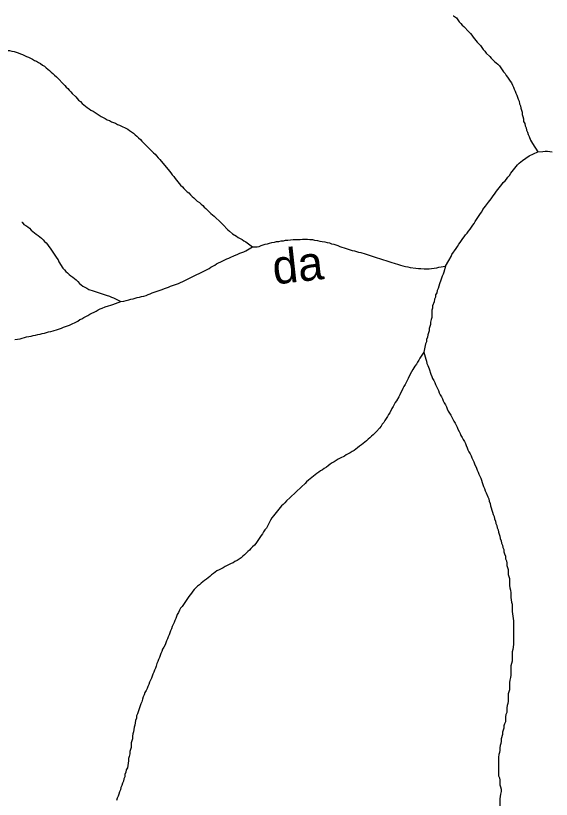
# Model space of a CAD drawing. Extents: x 652.3 to 678, y 7316.9 to 7344.9.
# Drawn here: x 675.65 to 676.905, y 7339.863 to 7341.699 of the extents above; entities that cross this region are included whole.
import ezdxf
from ezdxf.enums import TextEntityAlignment as Align

# ---------------------------------------------------------------- set-up
doc = ezdxf.new("R2010")
doc.units = 0
doc.header["$LTSCALE"] = 0.032
doc.layers.add('61', color=7, linetype='Continuous')
doc.layers.add('7', color=7, linetype='Continuous', lineweight=25)

msp = doc.modelspace()

# ---------------------------------------------------------------- linework, layer by layer
at = {"layer": '7'}
for points in [[(676.6749, 7341.6989), (676.6752, 7341.6987), (676.6824, 7341.6939), (676.6856, 7341.6892), (676.6888, 7341.6844), (676.6927, 7341.6804), (676.6959, 7341.6764), (676.6999, 7341.6733), (676.7118, 7341.6613), (676.715, 7341.6573), (676.7182, 7341.6534), (676.7214, 7341.6486), (676.7246, 7341.6446), (676.7309, 7341.6367), (676.7389, 7341.6287), (676.7421, 7341.6247), (676.7452, 7341.6199), (676.7492, 7341.616), (676.7524, 7341.6112), (676.7604, 7341.6032), (676.7635, 7341.5993), (676.7715, 7341.5913), (676.7755, 7341.5881), (676.7795, 7341.5849), (676.7834, 7341.581), (676.7866, 7341.577), (676.7898, 7341.5722), (676.793, 7341.5674), (676.7962, 7341.5634), (676.7986, 7341.5587), (676.8017, 7341.5547), (676.8081, 7341.5451), (676.8113, 7341.5412), (676.8137, 7341.5364), (676.8161, 7341.5316), (676.8177, 7341.5268), (676.82, 7341.5221), (676.8216, 7341.5173), (676.824, 7341.5125), (676.8272, 7341.503), (676.8296, 7341.4982), (676.8304, 7341.4926), (676.8328, 7341.4879), (676.8336, 7341.4823), (676.8368, 7341.4727), (676.8368, 7341.4672), (676.8383, 7341.4624), (676.8399, 7341.4568), (676.8399, 7341.4513), (676.8423, 7341.4465), (676.8431, 7341.4409), (676.8455, 7341.4361), (676.8463, 7341.4306), (676.8487, 7341.4258), (676.8503, 7341.4202), (676.8527, 7341.4154), (676.8558, 7341.4075), (676.8606, 7341.3995), (676.8734, 7341.3796)], [(675.6241, 7341.6176), (675.6353, 7341.6176), (675.6408, 7341.616), (675.6464, 7341.6152), (675.6559, 7341.612), (675.6607, 7341.6096), (675.6655, 7341.608), (675.675, 7341.6032)], [(675.675, 7341.6032), (675.6798, 7341.6016), (675.6894, 7341.5969), (675.6941, 7341.5937), (675.6989, 7341.5921), (675.7029, 7341.5889), (675.7077, 7341.5865), (675.7124, 7341.5833), (675.7172, 7341.5802), (675.7212, 7341.577), (675.7252, 7341.5738), (675.7292, 7341.5706), (675.7331, 7341.5666), (675.7371, 7341.5634), (675.7411, 7341.5595), (675.7451, 7341.5555), (675.765, 7341.5356), (675.7681, 7341.5316), (675.7721, 7341.5284), (675.7753, 7341.5245), (675.7793, 7341.5205), (675.7825, 7341.5165), (675.7904, 7341.5085), (675.7936, 7341.5046), (675.7968, 7341.5006), (675.8016, 7341.4974), (675.8055, 7341.4934), (675.8095, 7341.4902), (675.8135, 7341.4871), (675.8175, 7341.4839), (675.8222, 7341.4807), (675.8262, 7341.4775), (675.831, 7341.4751), (675.8358, 7341.4719), (675.8405, 7341.4688), (675.8453, 7341.4656), (675.8501, 7341.4624), (675.8549, 7341.46), (675.8596, 7341.4576), (675.8644, 7341.4552), (675.8692, 7341.4536), (675.874, 7341.4505), (675.8787, 7341.4489), (675.8835, 7341.4473), (675.8883, 7341.4441), (675.8931, 7341.4425), (675.9122, 7341.433), (675.9161, 7341.4298), (675.9209, 7341.4266), (675.9257, 7341.4234), (675.9297, 7341.4194), (675.9336, 7341.4162), (675.9376, 7341.4123), (675.9424, 7341.4091), (675.9456, 7341.4051), (675.9535, 7341.3971), (675.9567, 7341.3932), (675.9647, 7341.3852), (675.9687, 7341.3812), (675.9726, 7341.3773), (675.9766, 7341.3741), (675.9798, 7341.3701), (675.9838, 7341.3661), (675.9878, 7341.3621), (676.01, 7341.3343), (676.0132, 7341.3303), (676.0164, 7341.3263), (676.0204, 7341.3224), (676.0236, 7341.3176), (676.0363, 7341.3017), (676.0403, 7341.2977), (676.0434, 7341.2937), (676.0474, 7341.2897), (676.0514, 7341.2865), (676.0554, 7341.2834), (676.0594, 7341.2794), (676.0633, 7341.2754), (676.0673, 7341.2722), (676.0713, 7341.2682), (676.0753, 7341.2643), (676.0801, 7341.2611), (676.084, 7341.2571), (676.088, 7341.2539), (676.0912, 7341.2499), (676.0952, 7341.2468), (676.0991, 7341.2428), (676.1031, 7341.2396), (676.1071, 7341.2356), (676.1111, 7341.2324), (676.1151, 7341.2293), (676.131, 7341.2133), (676.135, 7341.2094), (676.1469, 7341.1974), (676.1509, 7341.1942), (676.158, 7341.1879), (676.1668, 7341.1823), (676.1708, 7341.1791), (676.1803, 7341.1744), (676.1843, 7341.1712), (676.1891, 7341.1688), (676.205, 7341.1569)], [(676.6569, 7341.1123), (676.6649, 7341.125), (676.6697, 7341.1346), (676.672, 7341.1393), (676.6816, 7341.1537), (676.6848, 7341.1584), (676.688, 7341.1632), (676.6911, 7341.1672), (676.6975, 7341.1767), (676.7007, 7341.1807), (676.7039, 7341.1855), (676.7078, 7341.1895), (676.711, 7341.1942), (676.7142, 7341.199), (676.7174, 7341.203), (676.7206, 7341.2078), (676.7238, 7341.2118), (676.7261, 7341.2165), (676.7325, 7341.2261), (676.7357, 7341.2309), (676.7389, 7341.2356), (676.7421, 7341.2396), (676.7445, 7341.2444), (676.7508, 7341.2523), (676.7572, 7341.2619), (676.7635, 7341.2698), (676.7667, 7341.2746), (676.7731, 7341.2826), (676.7763, 7341.2873), (676.789, 7341.3033), (676.7922, 7341.308), (676.7962, 7341.312), (676.7994, 7341.316), (676.8025, 7341.3208), (676.8065, 7341.3247), (676.8097, 7341.3295), (676.8256, 7341.3494), (676.8296, 7341.3534), (676.8336, 7341.3566), (676.8375, 7341.3598), (676.8447, 7341.3653), (676.8527, 7341.3701), (676.8734, 7341.3796)], [(676.8734, 7341.3796), (676.8845, 7341.3804), (676.8901, 7341.3812), (676.8956, 7341.3812), (676.9012, 7341.3804), (676.9068, 7341.3796)], [(675.6645, 7341.2153), (675.6647, 7341.2149), (675.6687, 7341.2094), (675.6735, 7341.207), (675.6782, 7341.2038), (675.6822, 7341.2006), (675.6862, 7341.1966), (675.6902, 7341.1935), (675.6941, 7341.1903), (675.6981, 7341.1871), (675.7021, 7341.1839), (675.7061, 7341.1807), (675.7101, 7341.1775), (675.714, 7341.1736), (675.7172, 7341.1696), (675.7212, 7341.1664), (675.7244, 7341.1624), (675.7276, 7341.1584), (675.7307, 7341.1545), (675.7339, 7341.1497), (675.7403, 7341.1401), (675.7427, 7341.1354), (675.7459, 7341.1306), (675.749, 7341.1266), (675.7506, 7341.1218), (675.7602, 7341.1075), (675.7642, 7341.1035), (675.7673, 7341.0996), (675.7713, 7341.0964), (675.7753, 7341.0924), (675.7793, 7341.0892), (675.7833, 7341.086), (675.7872, 7341.0829), (675.7912, 7341.0797), (675.7952, 7341.0757), (675.7992, 7341.0717), (675.8032, 7341.0685), (675.8071, 7341.0653), (675.8119, 7341.063), (675.8167, 7341.0606), (675.8215, 7341.0574), (675.831, 7341.0542), (675.8358, 7341.0526), (675.8501, 7341.0478), (675.8549, 7341.0463), (675.862, 7341.0439), (675.8692, 7341.0415), (675.874, 7341.0391), (675.8787, 7341.0375), (675.8962, 7341.0295)], [(676.205, 7341.1569), (676.2153, 7341.1569), (676.2201, 7341.1584), (676.2249, 7341.16), (676.2344, 7341.1632), (676.24, 7341.164), (676.2448, 7341.1656), (676.2503, 7341.1672), (676.2559, 7341.168), (676.2607, 7341.1696), (676.2662, 7341.1696), (676.2718, 7341.1712), (676.2774, 7341.1712), (676.2822, 7341.1728), (676.2877, 7341.1728), (676.2933, 7341.1736), (676.2997, 7341.1744), (676.3164, 7341.1744), (676.3219, 7341.1752), (676.3331, 7341.1752), (676.3386, 7341.1744), (676.345, 7341.1744), (676.3498, 7341.1728), (676.357, 7341.172), (676.3625, 7341.1704), (676.3681, 7341.1696), (676.3737, 7341.1688), (676.3792, 7341.1672), (676.3848, 7341.1664), (676.3896, 7341.164), (676.3951, 7341.1632), (676.4047, 7341.16), (676.4095, 7341.1584), (676.4238, 7341.1537), (676.4286, 7341.1521), (676.4381, 7341.1489), (676.4437, 7341.1481), (676.4532, 7341.1449), (676.4588, 7341.1441), (676.4683, 7341.1409), (676.4731, 7341.1393), (676.4874, 7341.1346), (676.4922, 7341.133), (676.5065, 7341.1282), (676.5113, 7341.1266), (676.5169, 7341.125), (676.5264, 7341.1218), (676.5312, 7341.1202), (676.5368, 7341.1187), (676.5463, 7341.1155), (676.5511, 7341.1139), (676.5567, 7341.1131), (676.563, 7341.1115), (676.5686, 7341.1107), (676.5742, 7341.1091), (676.5869, 7341.1075), (676.5933, 7341.1067), (676.5988, 7341.1067), (676.6068, 7341.1059), (676.6187, 7341.1059), (676.6243, 7341.1067), (676.6299, 7341.1075), (676.6362, 7341.1083), (676.641, 7341.1099), (676.6569, 7341.1123)], [(675.8962, 7341.0295), (675.9034, 7341.0303), (675.909, 7341.0311), (675.9145, 7341.0327), (675.9193, 7341.0343), (675.9249, 7341.0351), (675.9344, 7341.0383), (675.94, 7341.0391), (675.9448, 7341.0407), (675.9504, 7341.0415), (675.9551, 7341.0431), (675.9599, 7341.0455), (675.9647, 7341.047), (675.9695, 7341.0494), (675.979, 7341.0526), (675.9838, 7341.0542), (675.9933, 7341.0574), (675.9981, 7341.0598), (676.0076, 7341.063), (676.0124, 7341.0653), (676.0172, 7341.0669), (676.0315, 7341.0717), (676.0363, 7341.0733), (676.0411, 7341.0757), (676.0458, 7341.0781), (676.0506, 7341.0805), (676.0745, 7341.0924), (676.0793, 7341.0948), (676.1031, 7341.1067), (676.1071, 7341.1099), (676.1119, 7341.1123), (676.1167, 7341.1139), (676.1206, 7341.1171), (676.135, 7341.1242), (676.1397, 7341.1266), (676.1445, 7341.129), (676.1493, 7341.1306), (676.154, 7341.133), (676.1612, 7341.1362), (676.17, 7341.1401), (676.1747, 7341.1425), (676.1843, 7341.1457), (676.1891, 7341.1481), (676.205, 7341.1569)], [(676.6569, 7341.1123), (676.6529, 7341.098), (676.6514, 7341.0932), (676.649, 7341.0884), (676.6474, 7341.0836), (676.6458, 7341.0789), (676.6426, 7341.0709), (676.6394, 7341.0598), (676.637, 7341.055), (676.6362, 7341.0494), (676.6331, 7341.0447), (676.6331, 7341.0391), (676.6307, 7341.0343), (676.6299, 7341.0287), (676.6267, 7341.0192), (676.6267, 7341.0136), (676.6251, 7341.0089), (676.6251, 7340.9913), (676.6235, 7340.9866), (676.6219, 7340.981), (676.6219, 7340.9754), (676.6187, 7340.9659), (676.6187, 7340.9603), (676.6155, 7340.9508), (676.6148, 7340.9452), (676.6124, 7340.9404), (676.6124, 7340.9349), (676.61, 7340.9301), (676.606, 7340.9102)], [(675.648, 7340.9404), (675.6544, 7340.9412), (675.6599, 7340.942), (675.6647, 7340.9436), (675.6703, 7340.9444), (675.675, 7340.946), (675.6806, 7340.9468), (675.6862, 7340.9476), (675.691, 7340.9492), (675.6965, 7340.95), (675.7013, 7340.9516), (675.7069, 7340.9524), (675.7116, 7340.954), (675.7172, 7340.9547), (675.722, 7340.9563), (675.7268, 7340.9579), (675.7323, 7340.9587), (675.7379, 7340.9603), (675.7475, 7340.9635), (675.7522, 7340.9651), (675.757, 7340.9667), (675.7618, 7340.9691), (675.7761, 7340.9738), (675.7952, 7340.9834), (675.8, 7340.9866), (675.8047, 7340.9882), (675.8095, 7340.9913), (675.8191, 7340.9961), (675.8238, 7340.9993), (675.8382, 7341.0065), (675.8429, 7341.0096), (675.8477, 7341.012), (675.8525, 7341.0136), (675.8596, 7341.0168), (675.8676, 7341.0192), (675.8724, 7341.0208), (675.8772, 7341.0224), (675.8962, 7341.0295)], [(676.606, 7340.9102), (676.5965, 7340.8967), (676.5941, 7340.8919), (676.5909, 7340.8871), (676.5885, 7340.8823), (676.5853, 7340.8776), (676.5805, 7340.8696), (676.5742, 7340.8585), (676.5694, 7340.8489), (676.567, 7340.8441), (676.5622, 7340.8346), (676.5591, 7340.8298), (676.5567, 7340.825), (676.5495, 7340.8107), (676.5471, 7340.806), (676.5423, 7340.7964), (676.5392, 7340.7924), (676.5344, 7340.7829), (676.5312, 7340.7781), (676.5264, 7340.7686), (676.5232, 7340.7646), (676.5209, 7340.7598), (676.5177, 7340.755), (676.5145, 7340.7503), (676.5121, 7340.7455), (676.5081, 7340.7415), (676.5057, 7340.7367), (676.5018, 7340.7327), (676.4954, 7340.7248), (676.4874, 7340.7168), (676.4835, 7340.7137), (676.4795, 7340.7097), (676.4755, 7340.7065), (676.4715, 7340.7025), (676.4676, 7340.6993), (676.4636, 7340.6961), (676.4596, 7340.693), (676.4556, 7340.6898), (676.4508, 7340.6866), (676.4469, 7340.6834), (676.4429, 7340.6802), (676.4381, 7340.6778), (676.4333, 7340.6747), (676.4286, 7340.6723), (676.4238, 7340.6699), (676.4198, 7340.6667), (676.4103, 7340.6619), (676.4055, 7340.6595), (676.4007, 7340.6564), (676.3959, 7340.6532), (676.3912, 7340.6508), (676.3864, 7340.6476), (676.3816, 7340.6444), (676.3776, 7340.6412), (676.3729, 7340.6381), (676.3689, 7340.6349), (676.3641, 7340.6325), (676.3601, 7340.6293), (676.3554, 7340.6261), (676.3514, 7340.6229), (676.3474, 7340.6198), (676.3434, 7340.6166), (676.3394, 7340.6134), (676.3355, 7340.6102), (676.3315, 7340.6062), (676.3283, 7340.6023), (676.3196, 7340.5951)], [(676.606, 7340.9102), (676.6108, 7340.8943), (676.6124, 7340.8895), (676.6132, 7340.8839), (676.6155, 7340.8792), (676.6187, 7340.8712), (676.6227, 7340.8585), (676.6251, 7340.8537), (676.6267, 7340.8489), (676.6291, 7340.8441), (676.6315, 7340.8394), (676.6331, 7340.8346), (676.6354, 7340.8298), (676.6378, 7340.825), (676.6402, 7340.8203), (676.6418, 7340.8155), (676.6442, 7340.8107), (676.6474, 7340.806), (676.6498, 7340.8012), (676.6514, 7340.7964), (676.6537, 7340.7916), (676.6569, 7340.7869), (676.6593, 7340.7821), (676.6609, 7340.7773), (676.6633, 7340.7725), (676.6665, 7340.7678), (676.6689, 7340.763), (676.672, 7340.7582), (676.6736, 7340.7534), (676.676, 7340.7487), (676.6792, 7340.7439), (676.684, 7340.7343), (676.6856, 7340.7296), (676.6888, 7340.7248), (676.6911, 7340.72), (676.6927, 7340.7152), (676.6959, 7340.7105), (676.6983, 7340.7057), (676.7015, 7340.7009), (676.7039, 7340.6961), (676.7055, 7340.6914), (676.7078, 7340.6866), (676.7094, 7340.6818), (676.7118, 7340.6771), (676.7142, 7340.6723), (676.7166, 7340.6675), (676.7182, 7340.6627), (676.7206, 7340.658), (676.723, 7340.6532), (676.7246, 7340.6484), (676.7293, 7340.6389), (676.7309, 7340.6341), (676.7333, 7340.6293), (676.7349, 7340.6245), (676.7373, 7340.6198), (676.7397, 7340.615), (676.7445, 7340.6007), (676.746, 7340.5959), (676.7484, 7340.5911), (676.75, 7340.5855), (676.7524, 7340.5808), (676.7556, 7340.5712), (676.758, 7340.5665), (676.7588, 7340.5609), (676.7612, 7340.5561), (676.762, 7340.5505), (676.7635, 7340.5458), (676.7651, 7340.5402), (676.7667, 7340.5354), (676.7683, 7340.5298), (676.7707, 7340.5251)], [(676.3196, 7340.5951), (676.2925, 7340.5696), (676.2845, 7340.5617), (676.2806, 7340.5577), (676.2766, 7340.5537), (676.2726, 7340.5505), (676.2694, 7340.5466), (676.2662, 7340.5426), (676.2631, 7340.5386), (676.2599, 7340.5346), (676.2567, 7340.5306), (676.2535, 7340.5267), (676.2503, 7340.5219), (676.2471, 7340.5171), (676.2448, 7340.5123), (676.2424, 7340.5076), (676.24, 7340.5028), (676.2376, 7340.498), (676.2336, 7340.494), (676.2304, 7340.4893), (676.228, 7340.4845), (676.2249, 7340.4805), (676.2217, 7340.4765), (676.2185, 7340.4718), (676.2153, 7340.467), (676.2121, 7340.4622), (676.209, 7340.4582), (676.205, 7340.4543), (676.201, 7340.4503), (676.1978, 7340.4463), (676.1938, 7340.4431), (676.1899, 7340.4391), (676.1859, 7340.4352), (676.1819, 7340.432), (676.1779, 7340.4288), (676.1731, 7340.4256), (676.1684, 7340.4224), (676.1636, 7340.42), (676.1596, 7340.4169), (676.1548, 7340.4153), (676.1501, 7340.4129), (676.1453, 7340.4105), (676.1405, 7340.4081), (676.1357, 7340.4049), (676.131, 7340.4025), (676.1262, 7340.4002), (676.1214, 7340.3978), (676.1174, 7340.3946), (676.1135, 7340.3914), (676.1087, 7340.389), (676.1047, 7340.385), (676.1007, 7340.3819), (676.0968, 7340.3787), (676.092, 7340.3755), (676.088, 7340.3723), (676.084, 7340.3691), (676.0801, 7340.3651), (676.0761, 7340.362), (676.0721, 7340.358), (676.0681, 7340.354), (676.0649, 7340.35), (676.0617, 7340.346), (676.0586, 7340.3421), (676.0554, 7340.3381), (676.0522, 7340.3333), (676.049, 7340.3285), (676.0458, 7340.3238), (676.0427, 7340.319), (676.0395, 7340.3142), (676.0363, 7340.3102), (676.0339, 7340.3055), (676.0315, 7340.3007), (676.0283, 7340.2959), (676.0267, 7340.2911), (676.0251, 7340.2864), (676.0228, 7340.2816), (676.0212, 7340.2768), (676.0188, 7340.272), (676.0164, 7340.2673), (676.0148, 7340.2625), (676.0124, 7340.2577), (676.0108, 7340.2529), (676.0092, 7340.2482), (676.0068, 7340.2434), (676.0053, 7340.2386), (676.0029, 7340.2339), (676.0013, 7340.2291), (675.9997, 7340.2243), (675.9965, 7340.2195), (675.9941, 7340.2148), (675.9925, 7340.2092), (675.9901, 7340.2044), (675.9885, 7340.1996), (675.987, 7340.1949), (675.9846, 7340.1901), (675.983, 7340.1853), (675.9806, 7340.1805), (675.979, 7340.175), (675.9774, 7340.1702), (675.975, 7340.1654), (675.9734, 7340.1606)], [(676.7707, 7340.5251), (676.7715, 7340.5195), (676.7739, 7340.5147), (676.7747, 7340.5092), (676.7771, 7340.5044), (676.7779, 7340.4988), (676.7803, 7340.494), (676.7811, 7340.4885), (676.7826, 7340.4837), (676.7842, 7340.4789), (676.785, 7340.4734), (676.7874, 7340.4686), (676.7882, 7340.463), (676.7906, 7340.4582), (676.7914, 7340.4527), (676.7938, 7340.4479), (676.7938, 7340.4423), (676.7954, 7340.4375), (676.797, 7340.432), (676.797, 7340.4264), (676.7994, 7340.4216), (676.8001, 7340.4161), (676.8001, 7340.4105), (676.8033, 7340.4009), (676.8033, 7340.3898), (676.8065, 7340.3803), (676.8065, 7340.3635), (676.8073, 7340.358), (676.8089, 7340.3524), (676.8097, 7340.3468), (676.8097, 7340.3357), (676.8105, 7340.3301), (676.8113, 7340.3246), (676.8129, 7340.3198), (676.8129, 7340.3031), (676.8137, 7340.2975), (676.8145, 7340.2919), (676.8153, 7340.2864), (676.8161, 7340.2808), (676.8161, 7340.2251), (676.8145, 7340.214), (676.8129, 7340.2084), (676.8129, 7340.1861), (676.8113, 7340.1805), (676.8097, 7340.1758), (676.8097, 7340.1535), (676.8089, 7340.1479), (676.8073, 7340.1416), (676.8065, 7340.136), (676.8065, 7340.1193), (676.8049, 7340.1145), (676.8033, 7340.1097), (676.8033, 7340.093), (676.8025, 7340.0874), (676.8009, 7340.0827), (676.8001, 7340.0771), (676.8001, 7340.066), (676.7978, 7340.0612), (676.797, 7340.0556), (676.797, 7340.0445), (676.7954, 7340.0397), (676.7938, 7340.0349), (676.7938, 7340.0294), (676.7922, 7340.0246), (676.7906, 7340.0198), (676.7906, 7340.0142), (676.7874, 7340.0047), (676.7874, 7339.9991), (676.7866, 7339.9936), (676.785, 7339.9888), (676.7842, 7339.9832), (676.7842, 7339.9776), (676.7834, 7339.9721), (676.7818, 7339.9673), (676.7811, 7339.9617), (676.7811, 7339.918), (676.7834, 7339.9132), (676.7842, 7339.9076), (676.7842, 7339.8965), (676.7858, 7339.8917), (676.7874, 7339.8861), (676.7874, 7339.8806), (676.7858, 7339.875), (676.785, 7339.8694), (676.7842, 7339.8639), (676.7842, 7339.8471)], [(675.9734, 7340.1606), (675.971, 7340.1559), (675.9695, 7340.1511), (675.9679, 7340.1463), (675.9655, 7340.1416), (675.9631, 7340.1368), (675.9615, 7340.132), (675.9591, 7340.1272), (675.9575, 7340.1225), (675.9551, 7340.1177), (675.9527, 7340.1129), (675.9511, 7340.1073), (675.9488, 7340.1026), (675.9472, 7340.097), (675.9456, 7340.0914), (675.9432, 7340.0867), (675.9416, 7340.0819), (675.94, 7340.0771), (675.9384, 7340.0723), (675.9368, 7340.0676), (675.9352, 7340.0628), (675.9328, 7340.058), (675.9328, 7340.0524), (675.9305, 7340.0477), (675.9297, 7340.0421), (675.9289, 7340.0365), (675.9273, 7340.0317), (675.9265, 7340.0262), (675.9257, 7340.0206), (675.9241, 7340.0158), (675.9233, 7340.0103), (675.9233, 7340.0047), (675.9217, 7339.9999), (675.9201, 7339.9951), (675.9201, 7339.9896), (675.9201, 7339.984), (675.9185, 7339.9792), (675.9169, 7339.9745), (675.9169, 7339.9689), (675.9153, 7339.9633), (675.9138, 7339.9585), (675.9138, 7339.953), (675.913, 7339.9474), (675.9122, 7339.9418), (675.9114, 7339.9363), (675.909, 7339.9315), (675.9082, 7339.9259), (675.9058, 7339.9211), (675.9058, 7339.9156), (675.9034, 7339.9108), (675.9026, 7339.9052), (675.9002, 7339.9005), (675.8986, 7339.8949), (675.8962, 7339.8901), (675.8955, 7339.8845), (675.8931, 7339.8798), (675.8915, 7339.875), (675.8899, 7339.8702), (675.8875, 7339.8654), (675.8859, 7339.8599)]]:
    msp.add_lwpolyline(points, dxfattribs=at)

# ---------------------------------------------------------------- texts
at = {"layer": '61'}
msp.add_text('da', height=0.08, rotation=6.347, dxfattribs=at).set_placement((676.3147, 7341.0754), align=Align.CENTER)

doc.saveas('drawing.dxf')
